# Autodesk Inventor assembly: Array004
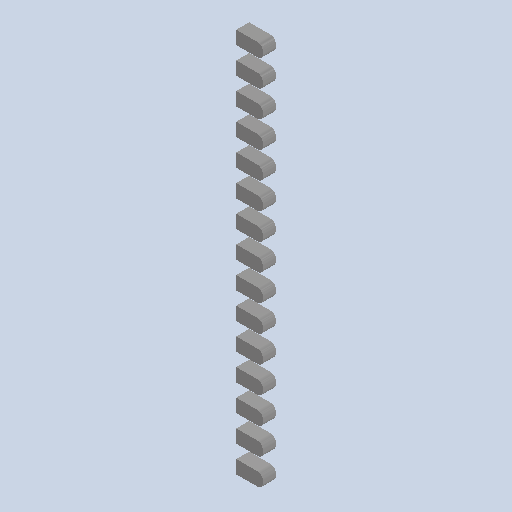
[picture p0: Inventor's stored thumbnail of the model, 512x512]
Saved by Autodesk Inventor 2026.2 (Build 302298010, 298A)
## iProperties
Created: 2026-10
Part Number: Array004
Document SubType Name: Assembly
Designer: mel
Author: mel
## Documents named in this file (16)
- D:\travail\année 2026-2027\1 sti2d IT\poubelle à verre\raspberry-pico-2-microcontroller-rp2350-1.snapshot.5\raspberry_pico_2\raspberry_pico_2\Array004.iam
- D:\travail\année 2026-2027\1 sti2d IT\poubelle à verre\raspberry-pico-2-microcontroller-rp2350-1.snapshot.5\raspberry_pico_2\raspberry_pico_2\Fillet.ipt
- D:\travail\année 2026-2027\1 sti2d IT\poubelle à verre\raspberry-pico-2-microcontroller-rp2350-1.snapshot.5\raspberry_pico_2\raspberry_pico_2\Fillet001.ipt
- D:\travail\année 2026-2027\1 sti2d IT\poubelle à verre\raspberry-pico-2-microcontroller-rp2350-1.snapshot.5\raspberry_pico_2\raspberry_pico_2\Fillet002.ipt
- D:\travail\année 2026-2027\1 sti2d IT\poubelle à verre\raspberry-pico-2-microcontroller-rp2350-1.snapshot.5\raspberry_pico_2\raspberry_pico_2\Fillet003.ipt
- D:\travail\année 2026-2027\1 sti2d IT\poubelle à verre\raspberry-pico-2-microcontroller-rp2350-1.snapshot.5\raspberry_pico_2\raspberry_pico_2\Fillet004.ipt
- D:\travail\année 2026-2027\1 sti2d IT\poubelle à verre\raspberry-pico-2-microcontroller-rp2350-1.snapshot.5\raspberry_pico_2\raspberry_pico_2\Fillet005.ipt
- D:\travail\année 2026-2027\1 sti2d IT\poubelle à verre\raspberry-pico-2-microcontroller-rp2350-1.snapshot.5\raspberry_pico_2\raspberry_pico_2\Fillet006.ipt
- D:\travail\année 2026-2027\1 sti2d IT\poubelle à verre\raspberry-pico-2-microcontroller-rp2350-1.snapshot.5\raspberry_pico_2\raspberry_pico_2\Fillet007.ipt
- D:\travail\année 2026-2027\1 sti2d IT\poubelle à verre\raspberry-pico-2-microcontroller-rp2350-1.snapshot.5\raspberry_pico_2\raspberry_pico_2\Fillet008.ipt
- D:\travail\année 2026-2027\1 sti2d IT\poubelle à verre\raspberry-pico-2-microcontroller-rp2350-1.snapshot.5\raspberry_pico_2\raspberry_pico_2\Fillet009.ipt
- D:\travail\année 2026-2027\1 sti2d IT\poubelle à verre\raspberry-pico-2-microcontroller-rp2350-1.snapshot.5\raspberry_pico_2\raspberry_pico_2\Fillet010.ipt
- D:\travail\année 2026-2027\1 sti2d IT\poubelle à verre\raspberry-pico-2-microcontroller-rp2350-1.snapshot.5\raspberry_pico_2\raspberry_pico_2\Fillet011.ipt
- D:\travail\année 2026-2027\1 sti2d IT\poubelle à verre\raspberry-pico-2-microcontroller-rp2350-1.snapshot.5\raspberry_pico_2\raspberry_pico_2\Fillet012.ipt
- D:\travail\année 2026-2027\1 sti2d IT\poubelle à verre\raspberry-pico-2-microcontroller-rp2350-1.snapshot.5\raspberry_pico_2\raspberry_pico_2\Fillet013.ipt
- D:\travail\année 2026-2027\1 sti2d IT\poubelle à verre\raspberry-pico-2-microcontroller-rp2350-1.snapshot.5\raspberry_pico_2\raspberry_pico_2\Fillet014.ipt
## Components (15 placed, 15 different names)
1. 2690
2. 2691
3. 2692
4. 2693
5. 2694
6. 2695
7. 2696
8. 2697
9. 2698
10. 2699
11. 2700
12. 2701
13. 2702
14. 2703
15. 2704
